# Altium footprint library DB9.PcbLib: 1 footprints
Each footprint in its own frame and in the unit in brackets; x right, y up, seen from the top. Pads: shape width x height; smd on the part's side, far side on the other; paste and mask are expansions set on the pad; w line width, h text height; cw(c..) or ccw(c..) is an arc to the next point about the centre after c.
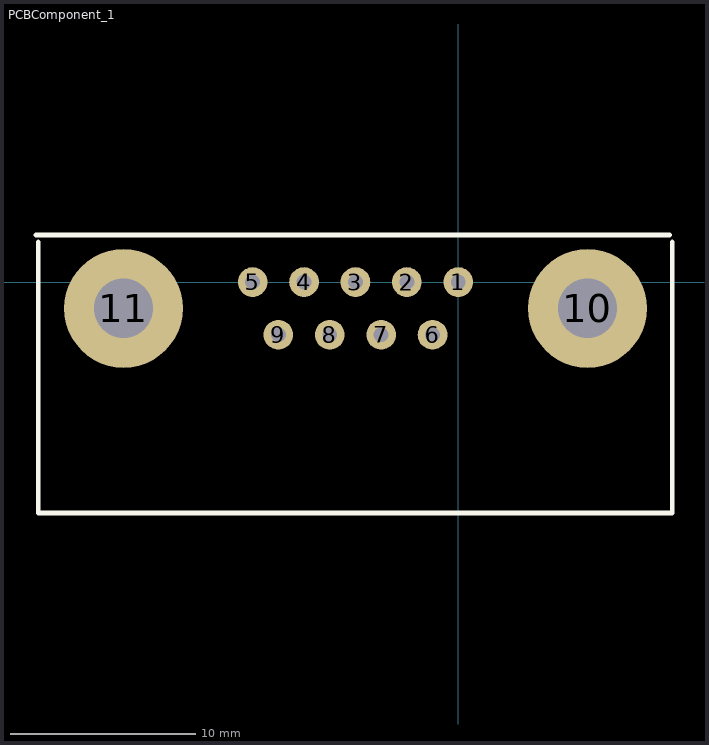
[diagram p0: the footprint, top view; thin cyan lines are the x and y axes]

## PCBComponent_1 [mm]
pads (11):
  round 1.6 hole 0.8: 1(0,0) 2(-2.77,0) 3(-5.54,0) 4(-8.31,0) 5(-11.08,0) 6(-1.385,-2.84) 7(-4.155,-2.84) 8(-6.925,-2.84) 9(-9.695,-2.84)
  round 6.4 hole 3.2: 10(6.96,-1.42) 11(-18.04,-1.42)
Top Overlay:
  lines w0.254: -22.764,2.54 11.399,2.54 ; -22.637,2.159 -22.637,-12.446 11.526,-12.446 11.526,2.159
